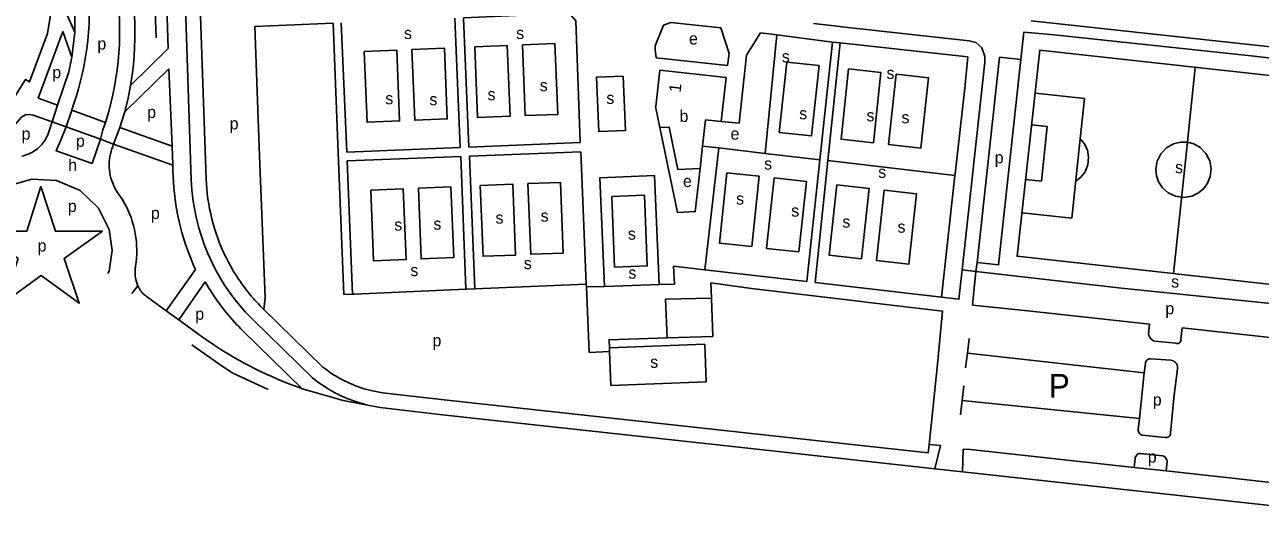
# Model space of a CAD drawing. Extents: x 161394 to 163917, y 388470 to 389774.
# Drawn here: x 162508 to 162922.4, y 388552.7 to 388716.6 of the extents above; entities that cross this region are included whole.
import ezdxf

# ---------------------------------------------------------------- set-up
doc = ezdxf.new("R2010")
doc.units = 0
for name, color, linetype in [('BLT_Basislijn', 7, 'Continuous'), ('BLT_Bebouwing', 7, 'Continuous'), ('BLT_Centroide', 7, 'Continuous'), ('BLT_Huisnummer', 7, 'Continuous'), ('BLT_Tekst_parkeren', 7, 'Continuous'), ('BLT_Vlakafsluiter', 7, 'Continuous')]:
    doc.layers.add(name, color=color, linetype=linetype)

msp = doc.modelspace()

# ---------------------------------------------------------------- linework, layer by layer
at = {"layer": 'BLT_Basislijn'}
for p, q in [((162555.37, 388731.17), (162556.16, 388708.53)), ((162566.73, 388728.42), (162568.91, 388664.72)), ((162561.79, 388726.76), (162563.92, 388664.51)), ((162521.83, 388720.73), (162524.91, 388714.01)), ((162611.46, 388717.08), (162613.21, 388673.69)), ((162614.13, 388717.19), (162616.07, 388673.8)), ((162652.33, 388718.79), (162654.08, 388675.36)), ((162655.22, 388718.91), (162656.98, 388675.48)), ((162520.87, 388714.24), (162512.6, 388691.9)), ((162520.87, 388714.24), (162523.8, 388705.72)), ((162760.25, 388713.2), (162756.41, 388673.42)), ((162779, 388710.76), (162760.25, 388713.2)), ((162543.56, 388696.2), (162556.16, 388708.53)), ((162779, 388710.76), (162774.75, 388671.29)), ((162777.4, 388670.98), (162781.55, 388710.49)), ((162781.55, 388710.49), (162779, 388710.76)), ((162824.33, 388705.74), (162781.55, 388710.49)), ((162719.82, 388705.45), (162743.79, 388702.87)), ((162541.64, 388687.32), (162556.42, 388701.78)), ((162556.42, 388701.78), (162557.47, 388675.78)), ((162900.62, 388702.23), (162897.98, 388677.26)), ((162512.6, 388691.9), (162519.09, 388689.57)), ((162863.45, 388691.81), (162846.98, 388693.56)), ((162863.45, 388691.81), (162862.02, 388678.34)), ((162523.84, 388687.86), (162535.16, 388683.8)), ((162510.87, 388686.25), (162517.22, 388683.97)), ((162850.98, 388682.38), (162845.8, 388682.93)), ((162850.98, 388682.38), (162849.05, 388664.09)), ((162521.9, 388682.29), (162533.41, 388678.16)), ((162539.96, 388682.07), (162557.47, 388675.78)), ((162862.02, 388678.31), (162859.19, 388651.69)), ((162537.88, 388676.55), (162557.73, 388669.42)), ((162557.47, 388675.78), (162557.73, 388669.42)), ((162616.07, 388673.8), (162654.08, 388675.36)), ((162656.98, 388675.48), (162694.37, 388677.01)), ((162740.84, 388675.23), (162735.39, 388675.86)), ((162740.84, 388675.23), (162736.18, 388634.36)), ((162740.84, 388675.23), (162756.41, 388673.42)), ((162897.97, 388677.16), (162893.3, 388633.14)), ((162613.33, 388670.82), (162613.21, 388673.69)), ((162613.33, 388670.82), (162615.06, 388626.1)), ((162654.3, 388672.4), (162616.16, 388670.93)), ((162616.16, 388670.93), (162617.99, 388626.22)), ((162654.3, 388672.4), (162656.03, 388627.82)), ((162694.54, 388673.94), (162657.25, 388672.51)), ((162657.25, 388672.51), (162658.97, 388627.94)), ((162694.54, 388673.94), (162695.46, 388651.91)), ((162756.41, 388673.42), (162774.75, 388671.29)), ((162774.75, 388671.29), (162770.35, 388630.41)), ((162773.11, 388630.09), (162777.4, 388670.98)), ((162777.4, 388670.98), (162819.99, 388666.03)), ((162819.99, 388666.03), (162815.51, 388625.2)), ((162849.05, 388664.09), (162843.77, 388664.65)), ((162859.19, 388651.69), (162842.53, 388653.45)), ((162696.39, 388629.52), (162695.46, 388651.91)), ((162827.42, 388636.81), (162827.08, 388633.77)), ((162565.33, 388634.42), (162555.52, 388620.66)), ((162770.35, 388630.41), (162736.18, 388634.36)), ((162822.44, 388634.32), (162827.08, 388633.77)), ((162827.08, 388633.77), (162825.94, 388622.56)), ((162827.08, 388633.77), (162827.98, 388633.69)), ((162568.55, 388630.33), (162559.79, 388617.56)), ((162658.97, 388627.94), (162696.39, 388629.52)), ((162702.45, 388628.81), (162696.43, 388628.61)), ((162738.15, 388629.97), (162738.4, 388624.9)), ((162815.51, 388625.2), (162773.11, 388630.09)), ((162555.52, 388620.66), (162548.77, 388625.56)), ((162588.68, 388624.99), (162588.25, 388621.05)), ((162615.06, 388626.1), (162617.99, 388626.22)), ((162617.99, 388626.22), (162618.61, 388626.25)), ((162618.61, 388626.25), (162656.03, 388627.82)), ((162656.03, 388627.82), (162656.17, 388627.83)), ((162656.17, 388627.83), (162658.97, 388627.94)), ((162722.98, 388624.47), (162738.4, 388624.9)), ((162722.98, 388624.47), (162723.55, 388611.59)), ((162787.63, 388623.86), (162751.74, 388628.09)), ((162559.79, 388617.56), (162555.52, 388620.66)), ((162588.25, 388621.05), (162608.02, 388601.76)), ((162787.63, 388623.86), (162791.17, 388623.44)), ((162567.71, 388611.81), (162559.79, 388617.56)), ((162584.76, 388617.47), (162604.61, 388598.11)), ((162885.26, 388616.17), (162884.91, 388612.86)), ((162581.25, 388613.91), (162601.15, 388594.5)), ((162896.18, 388614.95), (162895.83, 388611.13)), ((162704.19, 388606.93), (162704.15, 388608.17)), ((162824.81, 388611.32), (162824.2, 388606.41)), ((162887.06, 388610.42), (162894.07, 388609.75)), ((162697.35, 388606.65), (162704.19, 388606.93)), ((162824.2, 388606.41), (162823.59, 388601.49)), ((162824.2, 388606.41), (162883.52, 388599.85)), ((162892.4, 388604.04), (162885.66, 388604.53)), ((162883.52, 388599.85), (162881.87, 388584.55)), ((162883.87, 388603.03), (162883.52, 388599.85)), ((162893.48, 388591.34), (162894.69, 388601.29)), ((162823.01, 388595.45), (162822.42, 388590.57)), ((162892.31, 388579.72), (162893.48, 388591.34)), ((162822.42, 388590.57), (162821.83, 388585.69)), ((162822.42, 388590.57), (162881.87, 388584.55)), ((162881.87, 388584.55), (162881.47, 388580.84)), ((162883, 388578.91), (162890.39, 388578.16)), ((162745.53, 388575.13), (162813.27, 388567.65)), ((162813.27, 388567.65), (162815.15, 388575.5)), ((162822.58, 388566.63), (162822.83, 388574.18)), ((162880.41, 388571.01), (162880.18, 388568.02)), ((162882.24, 388572.81), (162889.68, 388571.96)), ((162822.58, 388566.63), (162813.27, 388567.65)), ((162949.02, 388552.72), (162822.58, 388566.63)), ((162880.18, 388568.02), (162890.83, 388567)), ((162891.14, 388570.17), (162890.83, 388567))]:
    msp.add_line(p, q, dxfattribs=at)
for points in [[(162547.2, 388850.46), (162549.44, 388787.2), (162547.93, 388774.53), (162546.67, 388768.1), (162546.83, 388765.36), (162548.25, 388759.6), (162550.62, 388753.55), (162552.08, 388712.21)], [(162845.56, 388717.84), (162986.69, 388702.51), (162990.99, 388702.67), (162992.2, 388703.12), (162994.43, 388705.08), (162995.77, 388707.96), (163006.5, 388806.58)], [(162504.76, 388692.48), (162508.27, 388698.15), (162509.67, 388697.38), (162515.69, 388713.62), (162516.59, 388719.1), (162516.71, 388731.13), (162517.37, 388777.82)], [(162524.43, 388774.07), (162524.66, 388760.48), (162524.77, 388749.73), (162524.91, 388714.01)], [(162537.72, 388735.49), (162538.26, 388732.69), (162538.73, 388729.88), (162539.12, 388727.05), (162539.43, 388724.21), (162539.66, 388721.36), (162539.81, 388718.51), (162539.89, 388715.66), (162539.88, 388712.81), (162539.79, 388709.95), (162539.62, 388707.1), (162539.37, 388704.26), (162539.04, 388701.42), (162538.63, 388698.6), (162538.15, 388695.79), (162537.58, 388692.99), (162536.94, 388690.21), (162536.22, 388687.44), (162535.16, 388683.8)], [(162529.64, 388724.93), (162529.72, 388722.18), (162529.71, 388719.43), (162529.63, 388716.69), (162529.46, 388713.95), (162529.22, 388711.21), (162528.9, 388708.48), (162528.49, 388705.76), (162528.01, 388703.06), (162527.45, 388700.37), (162526.81, 388697.7), (162526.1, 388695.04), (162525.31, 388692.41), (162524.43, 388689.81), (162523.84, 388687.86)], [(162544.24, 388726.11), (162544.55, 388723.26), (162544.78, 388720.41), (162544.93, 388717.55), (162545, 388714.68), (162544.99, 388711.82), (162544.9, 388708.96), (162544.74, 388706.1), (162544.49, 388703.25), (162544.16, 388700.4), (162543.56, 388696.2)], [(162694.37, 388677.01), (162692.86, 388717.9), (162690.62, 388720.38), (162655.22, 388718.91)], [(162611.46, 388717.08), (162585.25, 388715.98), (162586.74, 388672.6)], [(162743.79, 388702.87), (162744.33, 388706.91), (162741.52, 388715.48), (162724.73, 388717.34), (162722.33, 388716.43), (162719.5, 388709.46)], [(162779.58, 388716.17), (162772.53, 388716.95)], [(162782.12, 388715.89), (162779.58, 388716.17)], [(162824.83, 388711.15), (162782.12, 388715.89)], [(162524.91, 388714.01), (162523.8, 388705.72)], [(162760.25, 388713.2), (162754.85, 388713.79), (162750.07, 388706.33), (162747.65, 388683.59), (162741.66, 388684.15)], [(162958.93, 388619.41), (162958.75, 388622.34), (162951.75, 388623.34), (162956.74, 388667.01), (162960.25, 388701.33), (162919.31, 388706.11), (162853.31, 388713.16), (162843.1, 388714.01), (162842.12, 388704.94)], [(162621.94, 388707.58), (162622.87, 388683.87), (162633.79, 388684.3), (162632.86, 388708.01), (162621.94, 388707.58)], [(162637.93, 388708.25), (162638.86, 388684.53), (162649.77, 388684.96), (162648.84, 388708.68), (162637.93, 388708.25)], [(162658.98, 388709.13), (162659.91, 388685.41), (162670.83, 388685.84), (162669.9, 388709.55), (162658.98, 388709.13)], [(162674.97, 388709.79), (162675.9, 388686.08), (162686.81, 388686.5), (162685.88, 388710.22), (162674.97, 388709.79)], [(162719.5, 388709.46), (162719.44, 388708.21), (162719.82, 388705.45)], [(162824.83, 388711.15), (162826.98, 388710.56), (162829.06, 388708.81), (162830.09, 388705.85), (162830.07, 388704.03), (162822.44, 388634.32)], [(162523.8, 388705.72), (162522.82, 388700.75), (162519.09, 388689.57)], [(162763.62, 388704.03), (162761.07, 388680.43), (162771.92, 388679.26), (162774.47, 388702.85), (162763.62, 388704.03)], [(162824.33, 388705.74), (162823.38, 388695.28), (162820.04, 388666.52), (162819.99, 388666.03)], [(162827.42, 388636.81), (162835, 388705.67), (162842.12, 388704.94)], [(162842.12, 388704.94), (162834.68, 388635.98), (162827.42, 388636.81)], [(162784.37, 388701.73), (162781.82, 388678.13), (162792.67, 388676.96), (162795.22, 388700.56), (162784.37, 388701.73)], [(162800.32, 388699.95), (162797.77, 388676.35), (162808.62, 388675.18), (162811.17, 388698.78), (162800.32, 388699.95)], [(162543.56, 388696.2), (162542.7, 388691.94), (162541.64, 388687.32)], [(162519.09, 388689.57), (162517.22, 388683.97)], [(162523.84, 388687.86), (162521.9, 388682.29)], [(162541.64, 388687.32), (162541.34, 388686.38), (162539.96, 388682.07)], [(162510.87, 388686.25), (162509.61, 388686.46), (162508.35, 388686.31), (162507.01, 388685.54), (162503.02, 388681.07), (162498.79, 388677.01), (162494.25, 388673.31), (162488.61, 388669.52), (162483.41, 388666.77), (162481.14, 388665.29), (162479.49, 388663.98), (162478.46, 388662.9), (162478.12, 388662.41)], [(162517.22, 388683.97), (162515.67, 388679.32)], [(162535.16, 388683.8), (162534.3, 388681.28)], [(162515.67, 388679.32), (162515.41, 388678.8), (162515.13, 388678.28), (162514.83, 388677.78), (162514.49, 388677.29), (162514.13, 388676.81), (162513.74, 388676.35), (162513.33, 388675.9), (162512.89, 388675.48), (162512.43, 388675.08), (162511.96, 388674.7), (162511.46, 388674.34), (162510.95, 388674.02), (162510.42, 388673.71), (162509.88, 388673.44), (162509.33, 388673.2), (162508.78, 388672.99), (162508.21, 388672.8), (162507.65, 388672.64), (162507.09, 388672.52)], [(162521.9, 388682.29), (162520.02, 388677.59), (162518.58, 388674.32), (162530.71, 388670.03)], [(162534.3, 388681.28), (162533.41, 388678.16)], [(162539.96, 388682.07), (162537.88, 388676.55)], [(162734.54, 388668.31), (162732.93, 388653.88), (162726.92, 388653.6), (162721.09, 388682.07)], [(162862.02, 388678.32), (162863.4, 388676.67), (162864.42, 388674.55), (162864.86, 388672.09), (162864.59, 388669.56), (162863.65, 388667.25), (162862.21, 388665.39), (162860.51, 388664.07)], [(162533.41, 388678.16), (162530.71, 388670.03)], [(162537.88, 388676.55), (162537.55, 388675.75), (162537.25, 388674.93), (162536.99, 388674.08), (162536.77, 388673.21), (162536.6, 388672.33), (162536.48, 388671.43), (162536.4, 388670.52), (162536.38, 388669.61), (162536.4, 388668.69), (162536.47, 388667.78), (162536.59, 388666.87), (162536.76, 388665.97), (162536.98, 388665.08), (162537.24, 388664.22), (162537.55, 388663.37), (162537.9, 388662.55), (162538.29, 388661.75), (162538.71, 388660.98), (162539.17, 388660.25)], [(162537.2, 388674.73), (162537.15, 388674.59)], [(162897.94, 388677.16), (162895.71, 388677.2), (162893.3, 388676.62), (162890.97, 388675.31), (162889.05, 388673.3), (162887.82, 388670.84), (162887.36, 388668.26), (162887.59, 388665.87), (162888.32, 388663.83), (162889.6, 388661.89), (162891.51, 388660.2), (162893.98, 388659.05), (162896.73, 388658.65), (162899.42, 388659.07), (162901.73, 388660.16), (162903.5, 388661.66), (162904.77, 388663.41), (162905.66, 388665.64), (162905.95, 388668.25), (162905.45, 388670.96), (162904.17, 388673.42), (162902.31, 388675.33), (162900.15, 388676.57), (162898, 388677.15)], [(162586.74, 388672.6), (162586.85, 388669.81)], [(162557.73, 388669.42), (162557.75, 388667.53), (162557.81, 388665.64), (162557.92, 388663.75), (162558.07, 388661.86), (162558.26, 388659.96), (162558.49, 388658.08), (162558.77, 388656.19), (162559.08, 388654.31), (162559.45, 388652.44), (162559.85, 388650.58), (162560.3, 388648.72), (162560.79, 388646.88), (162561.31, 388645.05), (162561.88, 388643.24), (162562.49, 388641.44), (162563.15, 388639.65), (162563.83, 388637.89), (162564.56, 388636.14), (162565.33, 388634.42)], [(162586.85, 388669.81), (162588.68, 388624.99)], [(162720.77, 388629.42), (162719.29, 388665.98), (162700.98, 388665.24), (162702.45, 388628.81), (162720.77, 388629.42)], [(162743.55, 388666.93), (162741.01, 388643.33), (162751.86, 388642.16), (162754.4, 388665.76), (162743.55, 388666.93)], [(162537.38, 388640.89), (162536.34, 388647.86), (162532.8, 388654.99), (162526.62, 388660.91), (162518.66, 388664.3), (162510.47, 388664.71), (162503.37, 388662.7), (162497.64, 388659), (162492.72, 388653.1)], [(162563.92, 388664.51), (162564, 388662.88), (162564.14, 388661.07), (162564.32, 388659.26), (162564.55, 388657.44), (162564.83, 388655.63), (162565.16, 388653.83), (162565.54, 388652.03), (162565.96, 388650.24), (162566.43, 388648.47), (162566.95, 388646.7), (162567.51, 388644.95), (162568.12, 388643.22), (162568.77, 388641.5), (162569.47, 388639.8), (162570.21, 388638.13), (162570.99, 388636.48), (162571.82, 388634.85), (162572.68, 388633.25), (162573.58, 388631.67)], [(162568.91, 388664.72), (162568.99, 388663.2), (162569.12, 388661.51), (162569.29, 388659.83), (162569.51, 388658.14), (162569.76, 388656.46), (162570.07, 388654.79), (162570.42, 388653.12), (162570.81, 388651.46), (162571.25, 388649.81), (162571.73, 388648.17), (162572.25, 388646.54), (162572.82, 388644.93), (162573.42, 388643.34), (162574.07, 388641.76), (162574.76, 388640.21), (162575.48, 388638.68), (162576.25, 388637.17), (162577.05, 388635.68), (162577.89, 388634.21)], [(162640.07, 388661.74), (162641, 388638.02), (162651.92, 388638.45), (162650.99, 388662.17), (162640.07, 388661.74)], [(162660.83, 388662.61), (162661.76, 388638.89), (162672.68, 388639.32), (162671.75, 388663.04), (162660.83, 388662.61)], [(162676.82, 388663.28), (162677.75, 388639.56), (162688.66, 388639.99), (162687.73, 388663.7), (162676.82, 388663.28)], [(162759.36, 388665.16), (162756.81, 388641.56), (162767.66, 388640.39), (162770.21, 388663.99), (162759.36, 388665.16)], [(162780.43, 388662.84), (162777.88, 388639.25), (162788.73, 388638.07), (162791.28, 388661.67), (162780.43, 388662.84)], [(162545.2, 388635.63), (162545.39, 388636.96), (162545.52, 388638.3), (162545.6, 388639.66), (162545.63, 388641.02), (162545.59, 388642.4), (162545.5, 388643.77), (162545.35, 388645.15), (162545.13, 388646.52), (162544.86, 388647.88), (162544.53, 388649.23), (162544.14, 388650.56), (162543.7, 388651.88), (162543.2, 388653.17), (162542.65, 388654.43), (162542.04, 388655.67), (162541.39, 388656.87), (162540.69, 388658.03), (162539.95, 388659.16), (162539.17, 388660.25)], [(162624.09, 388661.07), (162625.02, 388637.36), (162635.93, 388637.78), (162635, 388661.5), (162624.09, 388661.07)], [(162704.97, 388658.97), (162705.9, 388635.26), (162716.81, 388635.69), (162715.89, 388659.4), (162704.97, 388658.97)], [(162796.27, 388661.07), (162793.72, 388637.47), (162804.57, 388636.3), (162807.12, 388659.9), (162796.27, 388661.07)], [(162535.98, 388633.18), (162536.34, 388633.92), (162537.38, 388640.89)], [(162545.2, 388635.63), (162545.15, 388635.28), (162545.1, 388634.93), (162545.07, 388634.58), (162545.05, 388634.22), (162545.04, 388633.87), (162545.04, 388633.51), (162545.05, 388633.15), (162545.07, 388632.8), (162545.1, 388632.44), (162545.14, 388632.08), (162545.2, 388631.73), (162545.26, 388631.38), (162545.33, 388631.03), (162545.42, 388630.68), (162545.51, 388630.34), (162545.62, 388629.99), (162545.73, 388629.66), (162545.85, 388629.33), (162545.98, 388629)], [(162577.89, 388634.21), (162578.33, 388633.48), (162578.8, 388632.73), (162579.28, 388631.98), (162579.77, 388631.24), (162580.27, 388630.51), (162580.78, 388629.79), (162581.3, 388629.07), (162581.83, 388628.36), (162582.37, 388627.65), (162582.91, 388626.95), (162583.47, 388626.26), (162584.04, 388625.58), (162584.61, 388624.91), (162585.2, 388624.24), (162585.79, 388623.59), (162586.4, 388622.94), (162587.01, 388622.3), (162587.63, 388621.66), (162588.28, 388621.02)], [(162720.77, 388629.42), (162725.93, 388629.52), (162725.65, 388635.57), (162736.18, 388634.36)], [(162822.44, 388634.32), (162821.37, 388624.52), (162815.51, 388625.2)], [(162958.93, 388619.41), (162941.26, 388621.48), (162875.88, 388628.23), (162827.98, 388633.69)], [(162548.77, 388625.56), (162548.58, 388625.7), (162548.39, 388625.84), (162548.21, 388625.99), (162548.03, 388626.14), (162547.86, 388626.3), (162547.69, 388626.47), (162547.52, 388626.64), (162547.36, 388626.81), (162547.21, 388626.99), (162547.06, 388627.18), (162546.92, 388627.37), (162546.78, 388627.56), (162546.65, 388627.76), (162546.52, 388627.96), (162546.4, 388628.16), (162546.29, 388628.37), (162546.18, 388628.58), (162546.08, 388628.79), (162545.98, 388629)], [(162568.55, 388630.33), (162569.81, 388628.24), (162570.35, 388627.38), (162570.91, 388626.52), (162571.47, 388625.67), (162572.04, 388624.82), (162572.63, 388623.98), (162573.23, 388623.15), (162573.84, 388622.33), (162574.46, 388621.52), (162575.1, 388620.72), (162575.74, 388619.92), (162576.4, 388619.13), (162577.06, 388618.36), (162577.74, 388617.59), (162578.42, 388616.83), (162579.12, 388616.08), (162579.82, 388615.34), (162580.53, 388614.62), (162581.25, 388613.91)], [(162573.58, 388631.67), (162574.07, 388630.86), (162574.58, 388630.05), (162575.09, 388629.25), (162575.62, 388628.46), (162576.16, 388627.67), (162576.71, 388626.89), (162577.27, 388626.11), (162577.84, 388625.35), (162578.42, 388624.59), (162579.01, 388623.84), (162579.61, 388623.09), (162580.22, 388622.36), (162580.84, 388621.63), (162581.47, 388620.92), (162582.11, 388620.21), (162582.76, 388619.51), (162583.42, 388618.82), (162584.08, 388618.14), (162584.76, 388617.47)], [(162696.43, 388628.61), (162696.39, 388629.52)], [(162697.35, 388606.65), (162696.43, 388628.61)], [(162751.74, 388628.09), (162738.15, 388629.97)], [(162723.55, 388611.59), (162738.77, 388612.02), (162738.4, 388624.9)], [(162812.01, 388582.12), (162814.19, 388602.69), (162815.85, 388620.53), (162791.17, 388623.44)], [(162825.94, 388622.56), (162844.46, 388620.59), (162885.26, 388616.17)], [(162896.18, 388614.95), (162946.23, 388609.43), (162954.12, 388608.78), (162956.18, 388608.77), (162957.86, 388610.21), (162958.93, 388619.41)], [(162884.91, 388612.86), (162885.03, 388612.38), (162885.23, 388611.92), (162885.5, 388611.5), (162885.84, 388611.13), (162886.23, 388610.82), (162886.66, 388610.57), (162887.06, 388610.42)], [(162564.12, 388609.24), (162573.12, 388602.79), (162577.64, 388599.85), (162589.74, 388594.27)], [(162567.71, 388611.81), (162569.39, 388610.63), (162571.09, 388609.47), (162572.8, 388608.34), (162574.53, 388607.24), (162576.29, 388606.16), (162578.06, 388605.11), (162579.84, 388604.08), (162581.65, 388603.09), (162583.47, 388602.12), (162585.3, 388601.18), (162587.15, 388600.27), (162589.01, 388599.39), (162590.89, 388598.54), (162592.77, 388597.72), (162594.68, 388596.93), (162596.59, 388596.17), (162598.51, 388595.44), (162600.43, 388594.75), (162601.15, 388594.5)], [(162704.15, 388608.17), (162704.04, 388610.9), (162723.55, 388611.59)], [(162704.15, 388608.17), (162736.09, 388609.39), (162736.57, 388596.82), (162704.63, 388595.6), (162704.19, 388606.93)], [(162894.07, 388609.75), (162894.38, 388609.65), (162894.69, 388609.64), (162895, 388609.71), (162895.29, 388609.85), (162895.53, 388610.05), (162895.71, 388610.32), (162895.82, 388610.61), (162895.85, 388610.93), (162895.83, 388611.13)], [(162885.66, 388604.53), (162885.29, 388604.51), (162884.94, 388604.42), (162884.61, 388604.25), (162884.33, 388604.02), (162884.11, 388603.73), (162883.95, 388603.4), (162883.87, 388603.03)], [(162892.4, 388604.04), (162892.84, 388603.95), (162893.26, 388603.79), (162893.65, 388603.55), (162893.99, 388603.25), (162894.27, 388602.9), (162894.49, 388602.5), (162894.63, 388602.07), (162894.69, 388601.63), (162894.69, 388601.29)], [(162608.02, 388601.76), (162609.34, 388600.78), (162610.15, 388600.2), (162610.98, 388599.63), (162611.83, 388599.09), (162612.69, 388598.56), (162613.56, 388598.06), (162614.45, 388597.57), (162615.34, 388597.11), (162616.25, 388596.67), (162617.17, 388596.25), (162618.1, 388595.85), (162619.03, 388595.48), (162619.98, 388595.13), (162620.93, 388594.8), (162621.88, 388594.49), (162622.84, 388594.21), (162623.81, 388593.96), (162624.71, 388593.74)], [(162604.61, 388598.11), (162605.49, 388597.42), (162606.38, 388596.74), (162607.3, 388596.09), (162608.23, 388595.46), (162609.17, 388594.85), (162610.13, 388594.27), (162611.11, 388593.7), (162612.1, 388593.16), (162613.1, 388592.64), (162614.12, 388592.15), (162615.15, 388591.68), (162616.18, 388591.23), (162617.23, 388590.82), (162618.29, 388590.42), (162619.35, 388590.05), (162620.42, 388589.71), (162621.5, 388589.4), (162622.58, 388589.11), (162623.66, 388588.85)], [(162614.87, 388590.5), (162603.93, 388593.64), (162601.15, 388594.5)], [(162811.34, 388575.79), (162811.04, 388573.01), (162648.77, 388590.72), (162628.06, 388593.11), (162624.71, 388593.74)], [(162623.66, 388588.85), (162614.87, 388590.5)], [(162745.53, 388575.13), (162648.21, 388585.76), (162627.31, 388588.16), (162623.66, 388588.85)], [(162811.34, 388575.79), (162812.01, 388582.12)], [(162881.47, 388580.84), (162881.46, 388580.47), (162881.53, 388580.11), (162881.67, 388579.77), (162881.89, 388579.47), (162882.16, 388579.22), (162882.48, 388579.04), (162882.84, 388578.93), (162883, 388578.91)], [(162890.39, 388578.16), (162890.73, 388578.1), (162891.07, 388578.12), (162891.4, 388578.22), (162891.71, 388578.39), (162891.96, 388578.62), (162892.15, 388578.91), (162892.27, 388579.23), (162892.32, 388579.57), (162892.31, 388579.72)], [(162815.15, 388575.5), (162811.34, 388575.79)], [(162822.83, 388574.18), (162825.28, 388574.11), (162880.18, 388568.02)], [(162880.41, 388571.01), (162880.49, 388571.4), (162880.65, 388571.77), (162880.88, 388572.1), (162881.16, 388572.38), (162881.5, 388572.6), (162881.88, 388572.74), (162882.24, 388572.81)], [(162889.68, 388571.96), (162890.05, 388571.82), (162890.39, 388571.61), (162890.68, 388571.34), (162890.9, 388571.01), (162891.06, 388570.65), (162891.14, 388570.17)], [(162890.83, 388567), (162951.14, 388560.26)]]:
    msp.add_lwpolyline(points, dxfattribs=at)
for points in [[(162953.12, 388696.46), (162848.54, 388708.06), (162840.86, 388638.91), (162945.45, 388627.3)], [(162708.77, 388699.31), (162709.57, 388681.14), (162700.57, 388680.74), (162699.78, 388698.92)], [(162493.07, 388647.3), (162508.75, 388647.3), (162513.5, 388662.26), (162518.32, 388647.3), (162534.11, 388647.35), (162521.27, 388638.16), (162526.33, 388623.16), (162513.58, 388632.48), (162500.91, 388623.26), (162505.83, 388638.13)]]:
    msp.add_lwpolyline(points, close=True, dxfattribs=at)
at = {"layer": 'BLT_Bebouwing'}
msp.add_line((162735.39, 388675.86), (162734.54, 388668.31), dxfattribs=at)
for points in [[(162719.7, 388689.15), (162721.07, 388701.37)], [(162721.07, 388701.37), (162743.26, 388698.86)], [(162743.26, 388698.86), (162741.66, 388684.15)], [(162721.09, 388682.07), (162719.64, 388689.15), (162719.7, 388689.15)], [(162741.66, 388684.15), (162741.59, 388684.07), (162736.37, 388684.65), (162735.39, 388675.86)], [(162734.54, 388668.31), (162727.12, 388667.95), (162724.22, 388682.21), (162721.09, 388682.07)]]:
    msp.add_lwpolyline(points, dxfattribs=at)
at = {"layer": 'BLT_Vlakafsluiter'}
for p, q in [((162521.9, 388682.29), (162517.22, 388683.97)), ((162533.41, 388678.16), (162537.88, 388676.55)), ((162543.94, 388626.41), (162545.98, 388629))]:
    msp.add_line(p, q, dxfattribs=at)

# ---------------------------------------------------------------- texts
at = {"layer": 'BLT_Centroide'}
for s, p in [('s', (162635.23, 388711.77)), ('s', (162672.87, 388711.77)), ('e', (162730.83, 388709.92)), ('p', (162532.42, 388708.22)), ('s', (162761.95, 388703.93)), ('p', (162517.31, 388698.64)), ('s', (162797.09, 388698.36)), ('s', (162680.75, 388694.24)), ('s', (162628.98, 388689.87)), ('s', (162643.77, 388689.53)), ('s', (162663.27, 388691.21)), ('s', (162703.11, 388689.98)), ('p', (162549.11, 388685.27)), ('b', (162727.65, 388683.94)), ('s', (162767.81, 388684.82)), ('s', (162790.34, 388684.15)), ('s', (162802.1, 388683.48)), ('p', (162576.79, 388681.46)), ('p', (162506.99, 388678.02)), ('p', (162525.23, 388675.63)), ('e', (162744.76, 388678.02)), ('h', (162522.62, 388667.48)), ('s', (162756.02, 388667.97)), ('p', (162833.35, 388670.07)), ('s', (162794.29, 388665.2)), ('s', (162893.83, 388666.77)), ('e', (162728.82, 388662.12)), ('s', (162746.63, 388656.23)), ('p', (162522.51, 388653.76)), ('p', (162550.36, 388651.39)), ('s', (162681.08, 388650.51)), ('s', (162765.12, 388652.2)), ('s', (162632, 388647.49)), ('s', (162645.11, 388647.82)), ('s', (162665.96, 388649.84)), ('s', (162782.27, 388648.5)), ('s', (162800.76, 388646.81)), ('s', (162710.33, 388644.46)), ('p', (162512.38, 388640.48)), ('s', (162675.42, 388634.58)), ('s', (162637.36, 388632.24)), ('s', (162710.51, 388631.39)), ('s', (162892.54, 388628.41)), ('p', (162565.23, 388617.61)), ('p', (162890.59, 388619.45)), ('p', (162644.8, 388608.71)), ('s', (162717.8, 388601.49)), ('p', (162886.37, 388588.84)), ('p', (162884.69, 388569.7))]:
    msp.add_text(s, height=4, dxfattribs=at).set_placement(p)
at = {"layer": 'BLT_Huisnummer'}
msp.add_text('1', height=4, rotation=83.8354, dxfattribs=at).set_placement((162728.01, 388693.71))
at = {"layer": 'BLT_Tekst_parkeren'}
msp.add_text('P', height=8, dxfattribs=at).set_placement((162851.42, 388591.44))

doc.saveas('drawing.dxf')
